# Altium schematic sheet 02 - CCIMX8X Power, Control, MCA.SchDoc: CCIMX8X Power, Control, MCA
size A3; PageSetup: Record=PageOptions¦CenterHorizontal=True¦CenterVertical=True¦PrintScale=0.70¦XCorrection=1.00¦YCorrection=1.00¦PrintKind=0¦BorderSize=5000000¦LeftOffset=0¦BottomOffset=0¦Orientation=2¦PaperLength=4200¦PaperWidth=2970¦Scale=100¦PaperSource=7¦PrintQuality=600¦MediaType=1¦DitherType=10¦PaperKind=A4¦PrintScaleMode=1; Author: Juan Anzola; SheetNumber: 2; SheetTotal: 17
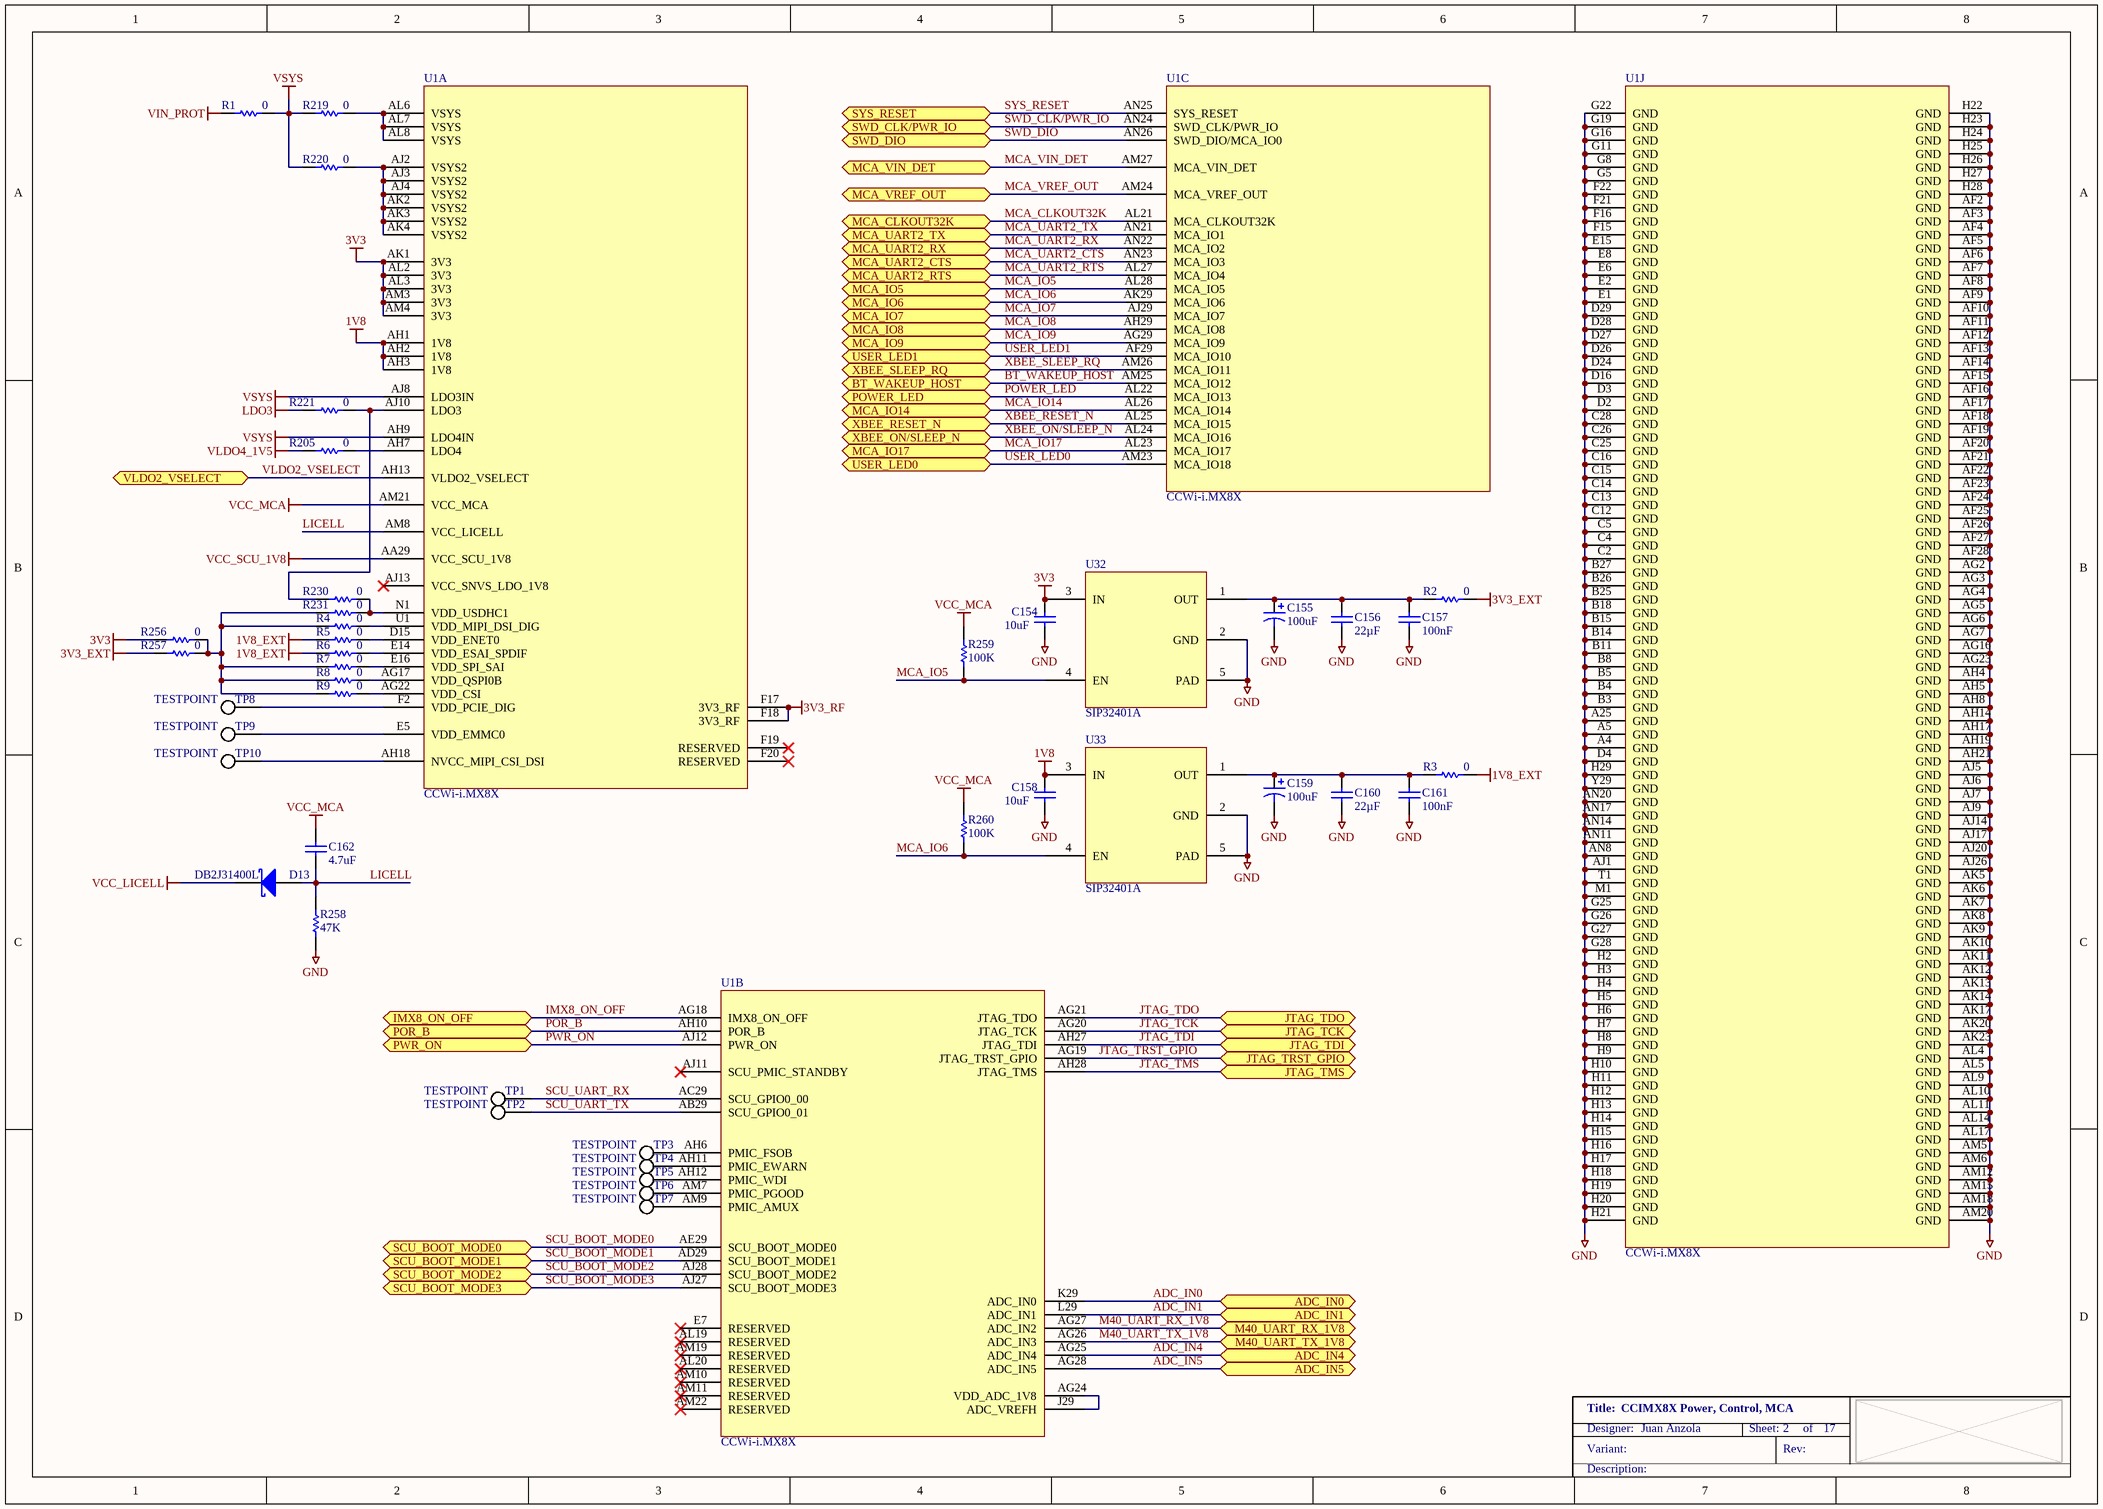
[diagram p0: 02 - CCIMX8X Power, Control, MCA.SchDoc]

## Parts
C154  10uF  [CAPC1005X55N]
C155  100uF  [CAPMP3216X120N]
C156  22µF  [CAPC1608X90N]
C157  100nF  [CAPC1005X55N]
C158  10uF  [CAPC1005X55N]
C159  100uF  [CAPMP3216X120N]
C160  22µF  [CAPC1608X90N]
C161  100nF  [CAPC1005X55N]
C162  4.7uF  [CAPC1005X55N]
D13  DB2J31400L  [SODFL2513X80N]
R1  0  [RESC2013X70N]
R2  0  [RESC1005X40N]
R3  0  [RESC1005X40N]
R4  0  [RESC1005X40N]
R5  0  [RESC1005X40N]
R6  0  [RESC1005X40N]
R7  0  [RESC1005X40N]
R8  0  [RESC1005X40N]
R9  0  [RESC1005X40N]
R205  0  [RESC1005X40N]
R219  0  [RESC1609X55N]
R220  0  [RESC1609X55N]
R221  0  [RESC1005X40N]
R230  0  [RESC1005X40N]
R231  0  [RESC1005X40N]
R256  0  [RESC1005X40N]
R257  0  [RESC1005X40N]
R258  47K  [RESC1005X40N]
R259  100K  [RESC1005X40N]
R260  100K  [RESC1005X40N]
TP1  TESTPOINT  [TP0762]  (no BOM)
TP2  TESTPOINT  [TP0762]  (no BOM)
TP3  TESTPOINT  [TP0762]  (no BOM)
TP4  TESTPOINT  [TP0762]  (no BOM)
TP5  TESTPOINT  [TP0762]  (no BOM)
TP6  TESTPOINT  [TP0762]  (no BOM)
TP7  TESTPOINT  [TP0762]  (no BOM)
TP8  TESTPOINT  [TP0762]  (no BOM)
TP9  TESTPOINT  [TP0762]  (no BOM)
TP10  TESTPOINT  [TP0762]  (no BOM)
U1  CCWi-i.MX8X  [CC8X_LGA]  (parts A,B,C,J of 10)
U32  SIP32401A  [SON50P120X160X60-5T55X91N]
U33  SIP32401A  [SON50P120X160X60-5T55X91N]

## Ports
ADC_IN0 (bidir), ADC_IN1 (bidir), ADC_IN4 (bidir), ADC_IN5 (bidir), BT_WAKEUP_HOST (bidir), IMX8_ON_OFF (bidir), JTAG_TCK (bidir), JTAG_TDI (bidir), JTAG_TDO (bidir), JTAG_TMS (bidir), JTAG_TRST_GPIO (bidir), M40_UART_RX_1V8 (bidir), M40_UART_TX_1V8 (bidir), MCA_CLKOUT32K (bidir), MCA_IO5 (bidir), MCA_IO6 (bidir), MCA_IO7 (bidir), MCA_IO8 (bidir), MCA_IO9 (bidir), MCA_IO14 (bidir), MCA_IO17 (bidir), MCA_UART2_CTS (bidir), MCA_UART2_RTS (bidir), MCA_UART2_RX (bidir), MCA_UART2_TX (bidir), MCA_VIN_DET (bidir), MCA_VREF_OUT (bidir), POR_B (bidir), POWER_LED (bidir), PWR_ON (bidir), SCU_BOOT_MODE0 (bidir), SCU_BOOT_MODE1 (bidir), SCU_BOOT_MODE2 (bidir), SCU_BOOT_MODE3 (bidir), SWD_CLK/PWR_IO (bidir), SWD_DIO (bidir), SYS_RESET (bidir), USER_LED0 (bidir), USER_LED1 (bidir), VLDO2_VSELECT (bidir), XBEE_ON/SLEEP_N (bidir), XBEE_RESET_N (bidir), XBEE_SLEEP_RQ (bidir)

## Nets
1V8: C158.2 U1.AH1(1V8) U1.AH2(1V8) U1.AH3(1V8) U33.3(IN)
1V8_EXT: R3.1 R5.1 R6.1
3V3: C154.2 R256.2 U1.AK1(3V3) U1.AL2(3V3) U1.AL3(3V3) U1.AM3(3V3) U1.AM4(3V3) U32.3(IN)
3V3_EXT: R2.1 R257.1
3V3_RF: U1.F17(3V3_RF) U1.F18(3V3_RF)
GND: C154.1 C155.2 C156.1 C157.1 C158.1 C159.2 C160.1 C161.1 R258.1 U1.A4(GND) U1.A5(GND) U1.A25(GND) U1.AF2(GND) U1.AF3(GND) U1.AF4(GND) U1.AF5(GND) U1.AF6(GND) U1.AF7(GND) U1.AF8(GND) U1.AF9(GND) U1.AF10(GND) U1.AF11(GND) U1.AF12(GND) U1.AF13(GND) U1.AF14(GND) U1.AF15(GND) U1.AF16(GND) U1.AF17(GND) U1.AF18(GND) U1.AF19(GND) U1.AF20(GND) U1.AF21(GND) U1.AF22(GND) U1.AF23(GND) U1.AF24(GND) U1.AF25(GND) U1.AF26(GND) U1.AF27(GND) U1.AF28(GND) U1.AG2(GND) U1.AG3(GND) U1.AG4(GND) U1.AG5(GND) U1.AG6(GND) U1.AG7(GND) U1.AG16(GND) U1.AG23(GND) U1.AH4(GND) U1.AH5(GND) U1.AH8(GND) U1.AH14(GND) U1.AH17(GND) U1.AH19(GND) U1.AH21(GND) U1.AJ1(GND) U1.AJ5(GND) U1.AJ6(GND) U1.AJ7(GND) U1.AJ9(GND) U1.AJ14(GND) U1.AJ17(GND) U1.AJ20(GND) U1.AJ26(GND) U1.AK5(GND) U1.AK6(GND) U1.AK7(GND) U1.AK8(GND) U1.AK9(GND) U1.AK10(GND) U1.AK11(GND) U1.AK12(GND) U1.AK13(GND) U1.AK14(GND) U1.AK17(GND) U1.AK20(GND) U1.AK23(GND) U1.AL4(GND) U1.AL5(GND) U1.AL9(GND) U1.AL10(GND) U1.AL11(GND) U1.AL14(GND) U1.AL17(GND) U1.AM5(GND) U1.AM6(GND) U1.AM12(GND) U1.AM15(GND) U1.AM18(GND) U1.AM20(GND) U1.AN8(GND) U1.AN11(GND) U1.AN14(GND) U1.AN17(GND) U1.AN20(GND) U1.B3(GND) U1.B4(GND) U1.B5(GND) U1.B8(GND) U1.B11(GND) U1.B14(GND) U1.B15(GND) U1.B18(GND) U1.B25(GND) U1.B26(GND) U1.B27(GND) U1.C2(GND) U1.C4(GND) U1.C5(GND) U1.C12(GND) U1.C13(GND) U1.C14(GND) U1.C15(GND) U1.C16(GND) U1.C25(GND) U1.C26(GND) U1.C28(GND) U1.D2(GND) U1.D3(GND) U1.D4(GND) U1.D16(GND) U1.D24(GND) U1.D26(GND) U1.D27(GND) U1.D28(GND) U1.D29(GND) U1.E1(GND) U1.E2(GND) U1.E6(GND) U1.E8(GND) U1.E15(GND) U1.F15(GND) U1.F16(GND) U1.F21(GND) U1.F22(GND) U1.G5(GND) U1.G8(GND) U1.G11(GND) U1.G16(GND) U1.G19(GND) U1.G22(GND) U1.G25(GND) U1.G26(GND) U1.G27(GND) U1.G28(GND) U1.H2(GND) U1.H3(GND) U1.H4(GND) U1.H5(GND) U1.H6(GND) U1.H7(GND) U1.H8(GND) U1.H9(GND) U1.H10(GND) U1.H11(GND) U1.H12(GND) U1.H13(GND) U1.H14(GND) U1.H15(GND) U1.H16(GND) U1.H17(GND) U1.H18(GND) U1.H19(GND) U1.H20(GND) U1.H21(GND) U1.H22(GND) U1.H23(GND) U1.H24(GND) U1.H25(GND) U1.H26(GND) U1.H27(GND) U1.H28(GND) U1.H29(GND) U1.M1(GND) U1.T1(GND) U1.Y29(GND) U32.2(GND) U32.5(PAD) U33.2(GND) U33.5(PAD)
LDO3: R221.1
VCC_LICELL: D13.K
VCC_MCA: C162.2 R259.2 R260.2 U1.AM21(VCC_MCA)
VCC_SCU_1V8: U1.AA29(VCC_SCU_1V8)
VIN_PROT: R1.1
VLDO4_1V5: R205.1
VSYS: R1.2 R219.1 R220.1 U1.AH9(LDO4IN) U1.AJ8(LDO3IN)
ADC_IN0: U1.K29(ADC_IN0) ; port ADC_IN0
ADC_IN1: U1.L29(ADC_IN1) ; port ADC_IN1
ADC_IN4: U1.AG25(ADC_IN4) ; port ADC_IN4
ADC_IN5: U1.AG28(ADC_IN5) ; port ADC_IN5
BT_WAKEUP_HOST: U1.AM25(MCA_IO12) ; port BT_WAKEUP_HOST
IMX8_ON_OFF: U1.AG18(IMX8_ON_OFF) ; port IMX8_ON_OFF
JTAG_TCK: U1.AG20(JTAG_TCK) ; port JTAG_TCK
JTAG_TDI: U1.AH27(JTAG_TDI) ; port JTAG_TDI
JTAG_TDO: U1.AG21(JTAG_TDO) ; port JTAG_TDO
JTAG_TMS: U1.AH28(JTAG_TMS) ; port JTAG_TMS
JTAG_TRST_GPIO: U1.AG19(JTAG_TRST_GPIO) ; port JTAG_TRST_GPIO
LICELL: C162.1 D13.A R258.2 U1.AM8(VCC_LICELL)
M40_UART_RX_1V8: U1.AG27(ADC_IN2) ; port M40_UART_RX_1V8
M40_UART_TX_1V8: U1.AG26(ADC_IN3) ; port M40_UART_TX_1V8
MCA_CLKOUT32K: U1.AL21(MCA_CLKOUT32K) ; port MCA_CLKOUT32K
MCA_IO5: R259.1 U1.AL28(MCA_IO5) U32.4(EN) ; port MCA_IO5
MCA_IO6: R260.1 U1.AK29(MCA_IO6) U33.4(EN) ; port MCA_IO6
MCA_IO7: U1.AJ29(MCA_IO7) ; port MCA_IO7
MCA_IO8: U1.AH29(MCA_IO8) ; port MCA_IO8
MCA_IO9: U1.AG29(MCA_IO9) ; port MCA_IO9
MCA_IO14: U1.AL26(MCA_IO14) ; port MCA_IO14
MCA_IO17: U1.AL23(MCA_IO17) ; port MCA_IO17
MCA_UART2_CTS: U1.AN23(MCA_IO3) ; port MCA_UART2_CTS
MCA_UART2_RTS: U1.AL27(MCA_IO4) ; port MCA_UART2_RTS
MCA_UART2_RX: U1.AN22(MCA_IO2) ; port MCA_UART2_RX
MCA_UART2_TX: U1.AN21(MCA_IO1) ; port MCA_UART2_TX
MCA_VIN_DET: U1.AM27(MCA_VIN_DET) ; port MCA_VIN_DET
MCA_VREF_OUT: U1.AM24(MCA_VREF_OUT) ; port MCA_VREF_OUT
POR_B: U1.AH10(POR_B) ; port POR_B
POWER_LED: U1.AL22(MCA_IO13) ; port POWER_LED
PWR_ON: U1.AJ12(PWR_ON) ; port PWR_ON
SCU_BOOT_MODE0: U1.AE29(SCU_BOOT_MODE0) ; port SCU_BOOT_MODE0
SCU_BOOT_MODE1: U1.AD29(SCU_BOOT_MODE1) ; port SCU_BOOT_MODE1
SCU_BOOT_MODE2: U1.AJ28(SCU_BOOT_MODE2) ; port SCU_BOOT_MODE2
SCU_BOOT_MODE3: U1.AJ27(SCU_BOOT_MODE3) ; port SCU_BOOT_MODE3
SCU_UART_RX: TP1.1 U1.AC29(SCU_GPIO0_00)
SCU_UART_TX: TP2.1 U1.AB29(SCU_GPIO0_01)
SWD_CLK/PWR_IO: U1.AN24(SWD_CLK/PWR_IO) ; port SWD_CLK/PWR_IO
SWD_DIO: U1.AN26(SWD_DIO/MCA_IO0) ; port SWD_DIO
SYS_RESET: U1.AN25(SYS_RESET) ; port SYS_RESET
USER_LED0: U1.AM23(MCA_IO18) ; port USER_LED0
USER_LED1: U1.AF29(MCA_IO10) ; port USER_LED1
VLDO2_VSELECT: U1.AH13(VLDO2_VSELECT) ; port VLDO2_VSELECT
XBEE_ON/SLEEP_N: U1.AL24(MCA_IO16) ; port XBEE_ON/SLEEP_N
XBEE_RESET_N: U1.AL25(MCA_IO15) ; port XBEE_RESET_N
XBEE_SLEEP_RQ: U1.AM26(MCA_IO11) ; port XBEE_SLEEP_RQ
NetC155_1: C155.1 C156.2 C157.2 R2.2 U32.1(OUT)
NetC159_1: C159.1 C160.2 C161.2 R3.2 U33.1(OUT)
NetR4_1: R4.1 R7.1 R8.1 R9.1 R231.2 R256.1 R257.2
NetR4_2: R4.2 U1.U1(VDD_MIPI_DSI_DIG)
NetR5_2: R5.2 U1.D15(VDD_ENET0)
NetR6_2: R6.2 U1.E14(VDD_ESAI_SPDIF)
NetR7_2: R7.2 U1.E16(VDD_SPI_SAI)
NetR8_2: R8.2 U1.AG17(VDD_QSPI0B)
NetR9_2: R9.2 U1.AG22(VDD_CSI)
NetR205_2: R205.2 U1.AH7(LDO4)
NetR219_2: R219.2 U1.AL6(VSYS) U1.AL7(VSYS) U1.AL8(VSYS)
NetR220_2: R220.2 U1.AJ2(VSYS2) U1.AJ3(VSYS2) U1.AJ4(VSYS2) U1.AK2(VSYS2) U1.AK3(VSYS2) U1.AK4(VSYS2)
NetR221_2: R221.2 R230.1 U1.AJ10(LDO3)
NetR230_2: R230.2 R231.1 U1.N1(VDD_USDHC1)
NetTP3_1: TP3.1 U1.AH6(PMIC_FSOB)
NetTP4_1: TP4.1 U1.AH11(PMIC_EWARN)
NetTP5_1: TP5.1 U1.AH12(PMIC_WDI)
NetTP6_1: TP6.1 U1.AM7(PMIC_PGOOD)
NetTP7_1: TP7.1 U1.AM9(PMIC_AMUX)
NetTP8_1: TP8.1 U1.F2(VDD_PCIE_DIG)
NetTP9_1: TP9.1 U1.E5(VDD_EMMC0)
NetTP10_1: TP10.1 U1.AH18(NVCC_MIPI_CSI_DSI)
NetU1_AG24: U1.AG24(VDD_ADC_1V8) U1.J29(ADC_VREFH)

Not connected (* = marked no-connect by the designer): U1 AJ11(SCU_PMIC_STANDBY)* AJ13(VCC_SNVS_LDO_1V8)* AL19(RESERVED)* AL20(RESERVED)* AM10(RESERVED)* AM11(RESERVED)* AM19(RESERVED)* AM22(RESERVED)* E7(RESERVED)* F19(RESERVED)* F20(RESERVED)*

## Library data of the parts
C154 C158 = 1001168: CAP CER 10UF 10V 20% X5R 0402; Part_Type: Capacitor; Manufacturer: Samsung; Manufacturer_Part_Number: CL05A106MP5NUNC; Digi_PN: 14050689; Component_Life_Cycle_State: Reviewed; Area: 0.95; Project: CCWMX6_SBC board
C155 C159 = 1001196: CAP TANT 100UF 6.3V 20% 1206; Part_Type: Capacitor; Manufacturer: Rohm; Manufacturer_Part_Number: TCTAL0J107M8R; Digi_PN: 14050490; Component_Life_Cycle_State: Reviewed; Area: 8.01; Project: CCWMX6_SBC board
C156 C160 = 1000998: CAP CER 22UF 10V 20% X5R 0603; Part_Type: Capacitor; Manufacturer: Samsung; Manufacturer_Part_Number: CL10A226MP8NUNE; Manufacturer_Alt_1: TDK Corporation; Manufacturer_Alt_1_Part_Number: C1608X5R1A226M080AC; Digi_PN: 14050684; Component_Life_Cycle_State: Reviewed; Area: 2.27; Project: ConnectCore i.MX6 module; Tolerance: 20
C157 C161 = 1000006: CAP 100nF 16V 10% X7R 0402; Part_Type: Capacitor; Manufacturer: Murata; Manufacturer_Part_Number: GRM155R71C104KA88D; Component_Life_Cycle_State: CAD Reviewed; Area: 0.95; Project: KITT; Tolerance: 10; Digi_PN: 14050552
C162 = 1000463: CAP CER 4.7UF 4V 20% X5R 0402; Part_Type: Capacitor; Manufacturer: Taiyo Yuden; Manufacturer_Part_Number: AMK105BJ475MV-F; Digi_PN: 14000071; Component_Life_Cycle_State: Reviewed; Area: 0,95
D13 = 1002592: DIODE SCHOTTKY 30V 30MA SMINI2; Part_Type: Diodes; Manufacturer: Panasonic - ECG; Digi_PN: 17000142; Component_Life_Cycle_State: Reviewed; Area: 6,06; Project: DIGI CC8X SOM
R1 = 1001557: RES 0.0 OHM 1/8W JUMP 0805 SMD; Part_Type: Resistor; Manufacturer: Yageo; Manufacturer_Part_Number: RC0805JR-070RL; Note: 13051095 = Digi No. for GE WDNU; Digi_PN: TR00037; Component_Life_Cycle_State: Reviewed; Area: 5,8; Project: WDNU-II; Power_WV_SRF: 125
R2-R9 R205 R221 R230 R231 R256 R257 = 1000076: RES 0.0 OHM 1/10W 0402 SMD; Part_Type: Resistor; Manufacturer: Panasonic - ECG; Manufacturer_Part_Number: ERJ-2GE0R00X; Digi_PN: 13050387; Component_Life_Cycle_State: Proven; Area: 0,95; Project: Adjustable Foundation; Power_WV_SRF: 10
R219 R220 = 1000208: RES 0.0 OHM 1/10W 0603; Part_Type: Resistor; Manufacturer: Panasonic - ECG; Manufacturer_Part_Number: ERJ-3GEY0R00V; Note: 13051103 = Digi No. for GE WDNU; Digi_PN: 13050568; Component_Life_Cycle_State: Reviewed; Area: 2,5; Project: Adjustable Foundation; Voltage: 75V
R258 = 1001155: RES 47.0K OHM 1/16W 1% 0402 SMD; Part_Type: Resistor; Manufacturer: Vishay Dale; Manufacturer_Part_Number: CRCW040247K0FKED; Digi_PN: 13050646; Component_Life_Cycle_State: Reviewed; Area: 0,95
R259 R260 = 1000480: RES 100K OHM 1/10W 1% 0402 SMD; Part_Type: Resistor; Manufacturer: Panasonic - ECG; Manufacturer_Part_Number: ERJ-2RKF1003X; Digi_PN: 13051063; Component_Life_Cycle_State: CAD Reviewed; Area: 0.95; Project: KITT; Power_WV_SRF: 100
TP1-TP10 = CAD0011: TEST POINT 30MIL PAD SMT; Component_Life_Cycle_State: Reviewed; Area: 0,58; Project: CLC
U1 = 1002581: ConnectCore for i.MX8X module - LGA; Manufacturer: DIGI; Manufacturer_Part_Number: 50001980-01; Digi_PN: CC-WMX-JM8E-NN; Component_Life_Cycle_State: Created; Area: 1800; Project: DIGI CC8X SOM
U32 U33 = 1001857: IC SW W/CTRL SLEW RATE 4TDFN; Manufacturer: Vishay Siliconix; Manufacturer_Part_Number: SIP32401ADNP-T1GE4; Component_Life_Cycle_State: Reviewed; Area: 4.93; Project: CCWMX6_SBC board; Digi_PN: 16052004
